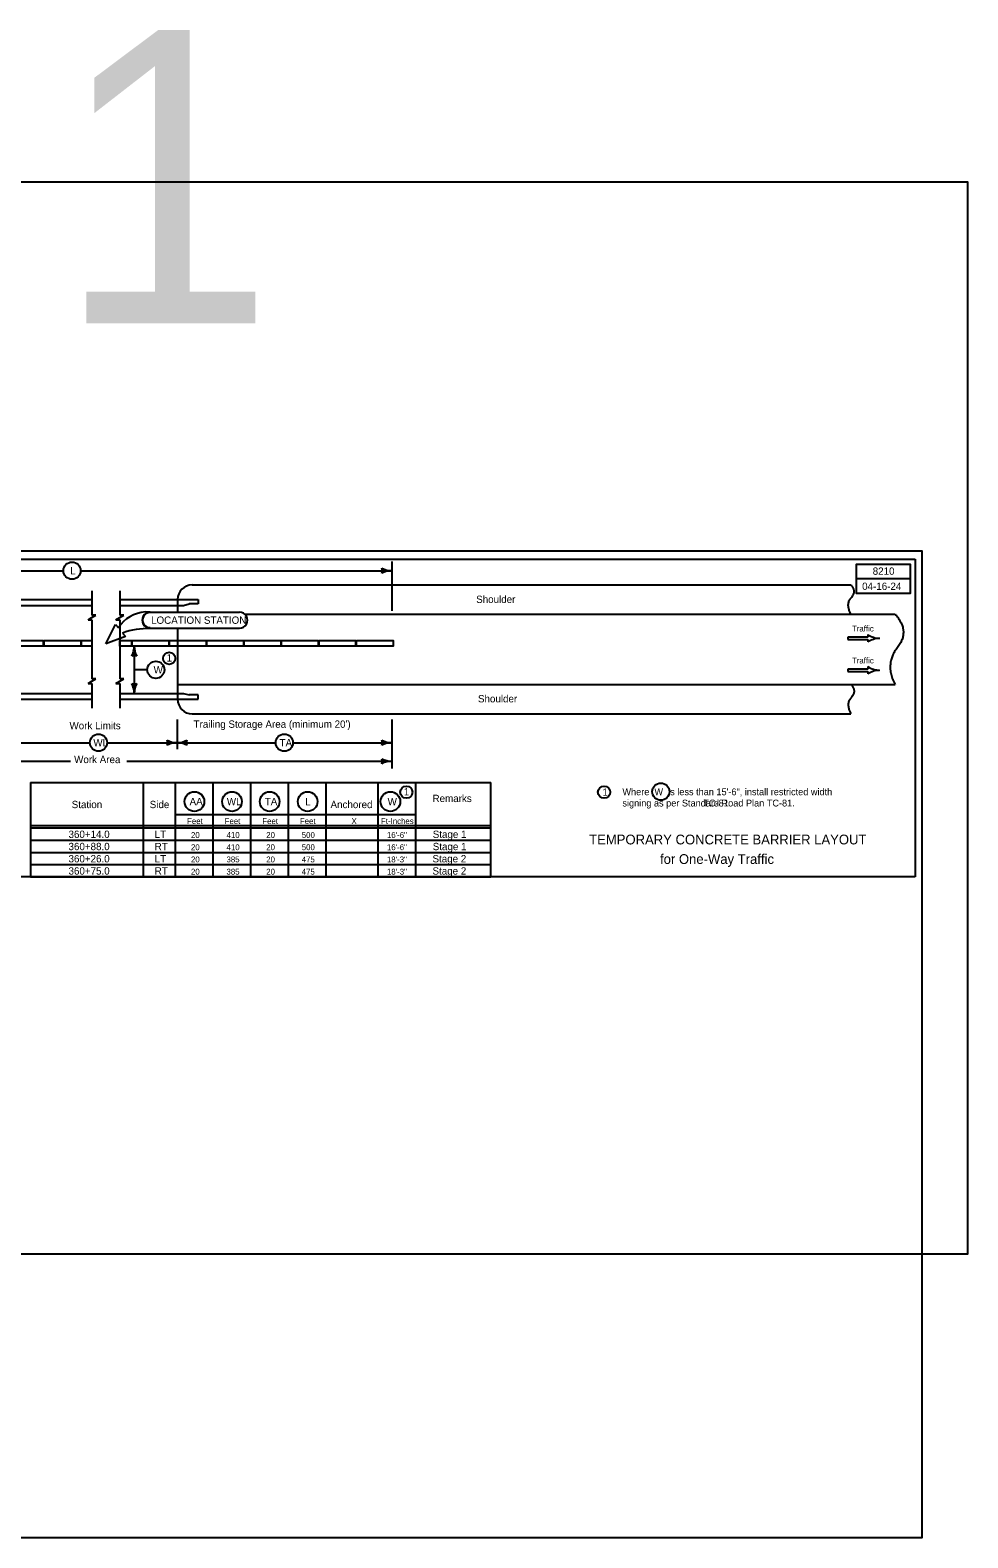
# Model space of a CAD drawing. Extents: x 10041 to 81668, y 7924 to 11018.
# Drawn here: x 11442 to 13362, y 7924 to 11009 of the extents above; entities that cross this region are included whole.
import ezdxf

# ---------------------------------------------------------------- set-up
doc = ezdxf.new("R2010")
doc.units = 0
for name, color, linetype in [('dsnCellElements', 7, 'Continuous'), ('dsnStdNameDate', 7, 'Continuous'), ('Level 1', 7, 'Continuous'), ('Level 10', 7, 'Continuous'), ('Level 12', 7, 'Continuous'), ('Level 4', 7, 'Continuous'), ('Level 5', 7, 'Continuous'), ('Level 6', 7, 'Continuous'), ('Level 63', 7, 'Continuous'), ('SheetAddendum', 7, 'Continuous'), ('SheetBorder', 7, 'Continuous'), ('SheetText', 7, 'Continuous')]:
    doc.layers.add(name, color=color, linetype=linetype)

msp = doc.modelspace()

# ---------------------------------------------------------------- linework, layer by layer
at = {"layer": 'dsnCellElements'}
msp.add_lwpolyline([(10041.2, 8505), (13362.1, 8505), (13362.1, 10698.4), (10041.2, 10698.4)], close=True, dxfattribs=at)
at = {"layer": 'Level 1'}
for p, q in [((12182.6, 9921.7), (12182.6, 9820.9)), ((10632, 9903.1), (11510.6, 9903.1)), ((11545.9, 9903.1), (12182.6, 9903.1)), ((11774.3, 9874.1), (13122.7, 9874.1)), ((11422.9, 9844.1), (11568.9, 9844.1)), ((11568.9, 9862.1), (11568.9, 9812.3)), ((11626, 9862.1), (11626, 9812.3)), ((11626, 9844.1), (11744.3, 9844.1)), ((11744.3, 9844.1), (11786.3, 9844.1)), ((11744.3, 9844.1), (11744.3, 9818.1)), ((11786.3, 9844.1), (11786.3, 9835.1)), ((11422.9, 9832.1), (11568.9, 9832.1)), ((11568.9, 9807.2), (11576.9, 9812.3)), ((11576.9, 9812.3), (11568.9, 9812.3)), ((11618, 9802.2), (11634, 9812.3)), ((11626, 9832.1), (11744.3, 9832.1)), ((11634, 9812.3), (11626, 9812.3)), ((11678.4, 9818.7), (11687.9, 9819)), ((11687.9, 9819), (11687.9, 9817.2)), ((11687.9, 9818.1), (11871, 9818.1)), ((11744.3, 9832.1), (11756.3, 9832.1)), ((11756.3, 9832.1), (11768.3, 9835.1)), ((11786.3, 9835.1), (11768.3, 9835.1)), ((11881.8, 9814.1), (13213.1, 9814.1)), ((11560.9, 9802.2), (11568.9, 9807.2)), ((11560.9, 9802.2), (11568.9, 9802.2)), ((11568.9, 9802.2), (11568.9, 9742.1)), ((11597.4, 9753.1), (11617.5, 9793.1)), ((11617.5, 9793.1), (11623.2, 9786.1)), ((11618, 9802.2), (11626, 9802.2)), ((11626, 9802.2), (11626, 9742.1)), ((11687.9, 9786.5), (11687.9, 9784.7)), ((11687.9, 9785.6), (11871, 9785.6)), ((11744.3, 9785.6), (11744.3, 9640.1)), ((11637.6, 9768.1), (11597.4, 9753.1)), ((11631.7, 9775.5), (11637.6, 9768.1)), ((13157.4, 9767), (13116.2, 9767)), ((13116.2, 9767), (13116.2, 9762.5)), ((13116.2, 9762.5), (13157.4, 9762.5)), ((13157.4, 9772.2), (13157.4, 9767)), ((13157.4, 9762.5), (13157.4, 9757.2)), ((13181.3, 9764.7), (13181.3, 9764.7)), ((11568.9, 9742.1), (11568.9, 9682.1)), ((11626, 9742.1), (11626, 9682.1)), ((11655.6, 9748.4), (11655.6, 9652.1)), ((11682.2, 9700.3), (11655.6, 9700.3)), ((13157.4, 9701.5), (13116.2, 9701.5)), ((13116.2, 9701.5), (13116.2, 9697)), ((13116.2, 9697), (13157.4, 9697)), ((13157.4, 9706.8), (13157.4, 9701.5)), ((13157.4, 9697), (13157.4, 9691.8)), ((13181.3, 9699.3), (13181.3, 9699.3)), ((11560.9, 9672), (11568.9, 9677)), ((11560.9, 9672), (11568.9, 9672)), ((11568.9, 9677), (11576.9, 9682.1)), ((11576.9, 9682.1), (11568.9, 9682.1)), ((11568.9, 9672), (11568.9, 9622.1)), ((11618, 9672), (11634, 9682.1)), ((11618, 9672), (11626, 9672)), ((11634, 9682.1), (11626, 9682.1)), ((11626, 9672), (11626, 9622.1)), ((11744.3, 9670.1), (13213.1, 9670.1)), ((11422.9, 9652.1), (11568.9, 9652.1)), ((11422.9, 9640.1), (11568.9, 9640.1)), ((11626, 9652.1), (11744.3, 9652.1)), ((11626, 9640.1), (11744.3, 9640.1)), ((11744.3, 9652.1), (11756.3, 9652.1)), ((11744.3, 9640.1), (11786.3, 9640.1)), ((11756.3, 9652.1), (11768.3, 9649.1)), ((11786.3, 9649.1), (11768.3, 9649.1)), ((11786.3, 9640.1), (11786.3, 9649.1)), ((11743.1, 9598.9), (11743.1, 9537.6)), ((11774.3, 9610.1), (13122.7, 9610.1)), ((12182.6, 9598.9), (12182.6, 9498)), ((11421.7, 9551.1), (11564.9, 9551.1)), ((11599.9, 9551.1), (11743.1, 9551.1)), ((11612.6, 9551.1), (11743.1, 9551.1)), ((11743.1, 9551.1), (11945.2, 9551.1)), ((11980.5, 9551.1), (12182.6, 9551.1)), ((10934.2, 9513.2), (11525, 9513.2)), ((11640.3, 9513.2), (12182.6, 9513.2)), ((11641.6, 9513.2), (11743.1, 9513.2)), ((11674.2, 9276.7), (11674.2, 9469.7)), ((11740.2, 9276.7), (11740.2, 9469.7)), ((11817.2, 9276.7), (11817.2, 9469.7)), ((11894.2, 9276.7), (11894.2, 9469.7)), ((11971.2, 9276.7), (11971.2, 9469.7)), ((11443.2, 9381.7), (12385.7, 9381.7)), ((11740.2, 9403.9), (12231.7, 9403.9)), ((11443.2, 9376.7), (12385.7, 9376.7))]:
    msp.add_line(p, q, dxfattribs=at)
for points in [[(11394.4, 9760.4), (11469.4, 9760.4), (11469.4, 9748.4), (11394.4, 9748.4)], [(11470.9, 9760.4), (11545.9, 9760.4), (11545.9, 9748.4), (11470.9, 9748.4)], [(11651.3, 9760.4), (11726.3, 9760.4), (11726.3, 9748.4), (11651.3, 9748.4)], [(11727.8, 9760.4), (11802.8, 9760.4), (11802.8, 9748.4), (11727.8, 9748.4)], [(11804.3, 9760.4), (11879.3, 9760.4), (11879.3, 9748.4), (11804.3, 9748.4)], [(11880.8, 9760.4), (11955.8, 9760.4), (11955.8, 9748.4), (11880.8, 9748.4)], [(11957.3, 9760.4), (12032.3, 9760.4), (12032.3, 9748.4), (11957.3, 9748.4)], [(12033.8, 9760.4), (12108.8, 9760.4), (12108.8, 9748.4), (12033.8, 9748.4)], [(12110.3, 9760.4), (12185.3, 9760.4), (12185.3, 9748.4), (12110.3, 9748.4)]]:
    msp.add_lwpolyline(points, close=True, dxfattribs=at)
for points in [[(11568.9, 9748.4), (11547.4, 9748.4), (11547.4, 9760.4), (11568.9, 9760.4)], [(11568.9, 9760.4), (11568.9, 9748.4)], [(11626, 9748.4), (11626, 9760.4)], [(11626, 9760.4), (11649.8, 9760.4), (11649.8, 9748.4), (11626, 9748.4)]]:
    msp.add_lwpolyline(points, dxfattribs=at)
for centre, radius in [((11528.2, 9903.1), 17.6), ((11727, 9723.7), 12.5), ((11699.8, 9700.3), 17.6), ((11582.4, 9551.1), 17.6), ((11962.8, 9551.1), 17.6), ((11778.7, 9430.7), 20.1), ((11855.7, 9430.7), 20.1), ((11932.7, 9430.7), 20.1), ((12010.5, 9430.7), 20.1), ((12179.9, 9430.7), 20.1), ((12212.6, 9449.9), 12.5), ((12617.4, 9449.9), 12.5), ((12733.5, 9451), 17.6)]:
    msp.add_circle(centre, radius, dxfattribs=at)
for centre, radius, start, end in [((12146.9, 9903.1), 16.4, 342.2666, 17.7333), ((12182.6, 9945.6), 42.5, 241.9275, 270), ((11774.3, 9844.1), 30, 90, 180), ((12182.6, 9860.6), 42.5, 90, 118.0725), ((13183.3, 9813), 48.4, 237.618, 267.648), ((13183.3, 9716.4), 48.4, 92.352, 122.382), ((11613.1, 9748.4), 42.5, 331.9275, 0), ((11655.6, 9712.8), 16.4, 72.2666, 107.7334), ((11698.1, 9748.4), 42.5, 180, 208.0725), ((13183.3, 9747.6), 48.4, 237.618, 267.648), ((13183.3, 9651), 48.4, 92.352, 122.382), ((11655.6, 9687.8), 16.4, 252.2666, 287.7334), ((11613.1, 9652.1), 42.5, 0, 28.0725), ((11698.1, 9652.1), 42.5, 151.9275, 180), ((11774.3, 9640.1), 30, 180, 270), ((11707.4, 9551.1), 16.4, 342.2666, 17.7333), ((11743.1, 9593.6), 42.5, 241.9275, 270), ((11743.1, 9508.6), 42.5, 90, 118.0725), ((11743.1, 9593.6), 42.5, 270, 298.0725), ((11743.1, 9508.6), 42.5, 61.9275, 90), ((11778.7, 9551.1), 16.4, 162.2666, 197.7334), ((12146.9, 9551.1), 16.4, 342.2666, 17.7333), ((12182.6, 9593.6), 42.5, 241.9275, 270), ((12182.6, 9508.6), 42.5, 90, 118.0725), ((12146.9, 9513.2), 16.4, 342.2666, 17.7333), ((12182.6, 9555.7), 42.5, 241.9275, 270), ((12182.6, 9470.7), 42.5, 90, 118.0725)]:
    msp.add_arc(centre, radius, start, end, dxfattribs=at)
for centre, major_axis, start_param, end_param in [((11682.9, 9748.4), (-70.8, 0), 4.776871, 5.71778), ((11687.9, 9801.9), (-16.3, 0), 4.712389, 7.853982), ((11687.9, 9801.9), (15.4, 0), 1.570796, 4.712389), ((11871, 9801.9), (16.3, 0), 4.712389, 7.853982), ((11685, 9628.7), (-156.9, 0), 4.694293, 5.059134)]:
    msp.add_ellipse(centre, major_axis=major_axis, ratio=0.995025, start_param=start_param, end_param=end_param, dxfattribs=at)
for points in [[(13122.7, 9874.1), (13134.5, 9860), (13110.9, 9835), (13122.2, 9814.2)], [(13213.1, 9814.1), (13244.5, 9779.7), (13191.1, 9711.7), (13213.1, 9670.1)], [(13123.2, 9670.1), (13135, 9656), (13111.4, 9631), (13122.7, 9610.1)]]:
    msp.add_open_spline(points, degree=2, dxfattribs=at)
at = {"layer": 'Level 10'}
for p, q in [((10149.1, 9926.7), (13254.1, 9926.7)), ((13254.1, 9926.7), (13254.1, 9276.7))]:
    msp.add_line(p, q, dxfattribs=at)
at = {"layer": 'Level 4'}
msp.add_lwpolyline([(13244.1, 9916.7), (13244.1, 9856.7), (13134.1, 9856.7), (13134.1, 9916.7), (13244.1, 9916.7), (13244.1, 9886.7), (13134.1, 9886.7)], dxfattribs=at)
at = {"layer": 'Level 5'}
msp.add_line((13254.1, 9276.7), (10149.1, 9276.7), dxfattribs=at)
at = {"layer": 'Level 63'}
for p, q in [((11443.2, 9469.7), (11443.2, 9276.7)), ((11443.2, 9469.7), (12385.7, 9469.7)), ((12048.2, 9276.7), (12048.2, 9469.7)), ((12154.7, 9276.7), (12154.7, 9469.7)), ((12231.7, 9276.7), (12231.7, 9469.7)), ((12385.7, 9276.7), (12385.7, 9469.7))]:
    msp.add_line(p, q, dxfattribs=at)
at = {"layer": 'SheetAddendum'}
for p, q in [((11443.2, 9351.7), (12385.7, 9351.7)), ((11443.2, 9326.7), (12385.7, 9326.7)), ((11443.2, 9301.7), (12385.7, 9301.7)), ((11443.2, 9276.7), (12385.7, 9276.7))]:
    msp.add_line(p, q, dxfattribs=at)
at = {"layer": 'SheetBorder'}
msp.add_lwpolyline([(10132.5, 9944), (13267.5, 9944), (13267.5, 7924), (10132.5, 7924)], close=True, dxfattribs=at)

# ---------------------------------------------------------------- texts
at = {"layer": 'dsnStdNameDate'}
for s, p in [('8210', (13167.3, 9894.7)), ('04-16-24', (13145.6, 9863.7))]:
    msp.add_text(s, height=15, dxfattribs=at).set_placement(p)
at = {"layer": 'Level 12'}
for s, height, p in [('L', 15, (11524.3, 9895.6)), ('Shoulder', 15, (12355.5, 9837)), ('LOCATION STATION', 15, (11690, 9794.4)), ('Traffic', 12, (13124.9, 9778.7)), ('1', 15, (11721.7, 9717.1)), ('Traffic', 12, (13124.9, 9713.3)), ('W', 15, (11695.2, 9692.8)), ('Shoulder', 15, (12359.2, 9633.6)), ("Trailing Storage Area (minimum 20')", 15, (11777, 9581.6)), ('Work Limits', 15, (11523, 9578.6)), ('WL', 15, (11571.9, 9543.6)), ('TA', 15, (11953, 9543.6)), ('Work Area', 15, (11532.5, 9509.3)), ('1', 15, (12207.4, 9443.3)), ('Remarks', 15, (12266.2, 9429.6)), ('1', 15, (12614, 9442.4)), ('Where  W  is less than 15\'-6", install restricted width', 14, (12654.9, 9443.6)), ('Station', 15, (11527.5, 9417.2)), ('Side', 15, (11687.2, 9417.2)), ('AA', 15, (11768.9, 9423.2)), ('WL', 15, (11845.1, 9423.2)), ('TA', 15, (11922.8, 9423.2)), ('L', 15, (12005.5, 9422.8)), ('Anchored', 15, (12057.4, 9417.2)), ('W', 15, (12174.3, 9422.8)), ('signing as per Standard Road Plan TC-81.', 14, (12654.9, 9420.6)), ('                                TC-81', 14, (12654.2, 9420.6)), ('Feet', 12, (11763.7, 9384.7)), ('Feet', 12, (11840.7, 9384.7)), ('Feet', 12, (11917.7, 9384.7)), ('Feet', 12, (11994.7, 9384.7)), ('X', 12, (12100.3, 9384.7)), ('Ft-Inches', 12, (12160.7, 9384.7)), ('360+14.0', 15, (11521, 9356.2)), ('LT', 15, (11697.4, 9356.2)), ('20', 12, (11771.7, 9356.2)), ('410', 12, (11844.5, 9356.2)), ('20', 12, (11925.7, 9356.2)), ('500', 12, (11998.5, 9356.2)), ('16\'-6"', 12, (12172.8, 9356.2)), ('Stage 1', 15, (12266.6, 9356.2)), ('360+88.0', 15, (11521, 9331.2)), ('360+26.0', 15, (11521, 9306.2)), ('RT', 15, (11697.4, 9331.2)), ('LT', 15, (11697.4, 9306.2)), ('20', 12, (11771.7, 9331.2)), ('20', 12, (11771.7, 9306.2)), ('410', 12, (11844.5, 9331.2)), ('385', 12, (11844.4, 9306.2)), ('20', 12, (11925.7, 9331.2)), ('20', 12, (11925.7, 9306.2)), ('475', 12, (11998.4, 9306.2)), ('500', 12, (11998.5, 9331.2)), ('16\'-6"', 12, (12172.8, 9331.2)), ('18\'-3"', 12, (12172.8, 9306.2)), ('Stage 2', 15, (12266.1, 9306.2)), ('Stage 1', 15, (12266.6, 9331.2)), ('360+75.0', 15, (11521, 9281.2)), ('RT', 15, (11697.4, 9281.2)), ('20', 12, (11771.7, 9281.2)), ('385', 12, (11844.4, 9281.2)), ('20', 12, (11925.7, 9281.2)), ('475', 12, (11998.4, 9281.2)), ('18\'-3"', 12, (12172.8, 9281.2)), ('Stage 2', 15, (12266.1, 9281.2))]:
    msp.add_text(s, height=height, dxfattribs=at).set_placement(p)
at = {"layer": 'Level 6'}
for s, p in [('TEMPORARY CONCRETE BARRIER LAYOUT', (12586.8, 9343)), ('for One-Way Traffic', (12731.9, 9303))]:
    msp.add_text(s, height=20, dxfattribs=at).set_placement(p)
at = {"layer": 'SheetText'}
msp.add_text('1', height=600, dxfattribs=at).set_placement((11496.6, 10409.2))

doc.saveas('drawing.dxf')
